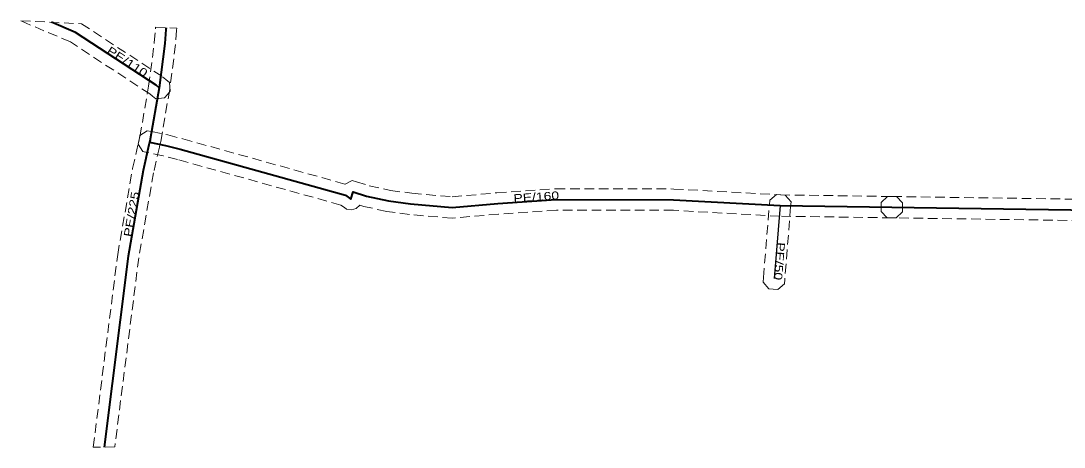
# Model space of a CAD drawing. Extents: x -701169 to -699809, y -1012430 to -1012137.
# Drawn here: x -700200.2 to -700102.4, y -1012429.8 to -1012389.8 of the extents above; entities that cross this region are included whole.
import ezdxf

# ---------------------------------------------------------------- set-up
doc = ezdxf.new("R2010")
doc.units = 0
doc.header["$LTSCALE"] = 0.3
doc.linetypes.add('MEDIUM_DASHED', pattern=[4.5, 3, -1.5])
doc.layers.add('1', color=7, linetype='MEDIUM_DASHED', lineweight=13)
doc.layers.add('24', color=7, linetype='Continuous', lineweight=40)
doc.layers.add('30', color=7, linetype='Continuous')

msp = doc.modelspace()

# ---------------------------------------------------------------- linework, layer by layer
at = {"layer": '1'}
for points in [[(-700200.203, -1012389.825), (-700194.524, -1012390.095), (-700186.926, -1012395.063), (-700186.604, -1012395.33), (-700186.284, -1012395.593), (-700186.205, -1012396.418), (-700186.469, -1012396.737), (-700186.732, -1012397.057), (-700187.557, -1012397.136), (-700187.876, -1012396.872), (-700188.114, -1012396.677), (-700195.564, -1012391.805)], [(-700191.401, -1012429.776), (-700193.419, -1012429.793), (-700191.129, -1012411.742), (-700189.731, -1012403.674), (-700189.179, -1012401.245), (-700189.123, -1012400.954), (-700189.045, -1012400.69), (-700189.044, -1012400.687), (-700188.229, -1012395.952), (-700187.695, -1012391.847), (-700187.597, -1012390.56), (-700187.587, -1012390.426), (-700185.589, -1012390.521), (-700185.603, -1012390.712), (-700185.705, -1012392.053), (-700186.251, -1012396.25), (-700187.095, -1012401.151), (-700187.129, -1012401.262), (-700187.177, -1012401.426), (-700187.221, -1012401.655), (-700187.769, -1012404.066), (-700189.151, -1012412.038)], [(-700185.01, -1012400.894), (-700169.822, -1012405.127), (-700169.136, -1012404.786), (-700168.752, -1012404.905), (-700167.542, -1012405.283), (-700165.566, -1012405.724), (-700163.56, -1012405.986), (-700159.781, -1012406.326), (-700155.589, -1012405.943), (-700150.073, -1012405.57), (-700138.992, -1012405.59), (-700129.015, -1012406.14), (-700118.547, -1012406.293), (-700118.133, -1012406.299), (-700117.556, -1012406.894), (-700117.562, -1012407.308), (-700117.568, -1012407.722), (-700118.163, -1012408.299), (-700118.577, -1012408.293), (-700129.085, -1012408.14), (-700139.048, -1012407.59), (-700150.007, -1012407.57), (-700155.431, -1012407.937), (-700159.779, -1012408.334), (-700163.78, -1012407.974), (-700165.914, -1012407.696), (-700168.058, -1012407.217), (-700168.437, -1012407.099), (-700168.77, -1012407.417), (-700168.996, -1012407.486), (-700169.222, -1012407.555), (-700169.688, -1012407.477), (-700169.879, -1012407.338), (-700170.213, -1012407.095), (-700185.53, -1012402.826), (-700186.878, -1012402.474), (-700188.352, -1012402.169), (-700188.758, -1012402.085), (-700189.213, -1012401.394), (-700189.129, -1012400.988), (-700189.045, -1012400.582), (-700188.354, -1012400.127), (-700187.948, -1012400.211), (-700186.422, -1012400.526)], [(-700128.02, -1012406.807), (-700128.053, -1012407.22), (-700128.603, -1012414.06), (-700128.636, -1012414.473), (-700129.267, -1012415.01), (-700129.68, -1012414.977), (-700130.093, -1012414.944), (-700130.63, -1012414.313), (-700130.597, -1012413.9), (-700130.047, -1012407.06), (-700130.014, -1012406.647), (-700129.383, -1012406.11), (-700128.97, -1012406.143), (-700128.557, -1012406.176)]]:
    msp.add_lwpolyline(points, close=True, dxfattribs=at)
msp.add_lwpolyline([(-700002.913, -1012408.1), (-700032.013, -1012408.18), (-700040.555, -1012408.28), (-700045.578, -1012408.37), (-700047.721, -1012408.47), (-700077.188, -1012408.81), (-700091.342, -1012408.69), (-700118.577, -1012408.293), (-700118.991, -1012408.287), (-700119.568, -1012407.692), (-700119.562, -1012407.278), (-700119.556, -1012406.864), (-700118.961, -1012406.287), (-700118.547, -1012406.293), (-700091.318, -1012406.69), (-700077.192, -1012406.81), (-700047.779, -1012406.47), (-700045.642, -1012406.37), (-700040.585, -1012406.28), (-700032.027, -1012406.18), (-700002.887, -1012406.1)], dxfattribs=at)
at = {"layer": '24', "lineweight": 25}
msp.add_line((-700129.05, -1012407.14), (-700129.6, -1012413.98), dxfattribs=at)
at = {"layer": '24'}
for points in [[(-700187.24, -1012396.101), (-700187.52, -1012395.87), (-700195.09, -1012390.92), (-700197.336, -1012389.962)], [(-700186.588, -1012390.473), (-700186.6, -1012390.636), (-700186.7, -1012391.95), (-700187.24, -1012396.101), (-700188.07, -1012400.92), (-700188.087, -1012400.976), (-700188.15, -1012401.19), (-700188.2, -1012401.45), (-700188.75, -1012403.87), (-700190.14, -1012411.89), (-700192.41, -1012429.785)], [(-700118.562, -1012407.293), (-700091.33, -1012407.69), (-700077.19, -1012407.81), (-700047.75, -1012407.47), (-700045.61, -1012407.37), (-700040.57, -1012407.28), (-700032.02, -1012407.18), (-700002.9, -1012407.1), (-699984.94, -1012407.63), (-699970.64, -1012408.03), (-699952.89, -1012407.83), (-699944.26, -1012407.4), (-699939.86, -1012407.09), (-699903.84, -1012405.22), (-699856.61, -1012400.09), (-699836.62, -1012397.69), (-699817.82, -1012395.72), (-699809.132, -1012395.385)], [(-700188.15, -1012401.19), (-700186.65, -1012401.5), (-700185.27, -1012401.86), (-700169.77, -1012406.18), (-700169.29, -1012406.53), (-700169.05, -1012405.86), (-700167.8, -1012406.25), (-700165.74, -1012406.71), (-700163.67, -1012406.98), (-700159.78, -1012407.33), (-700155.51, -1012406.94), (-700150.04, -1012406.57), (-700139.02, -1012406.59), (-700129.05, -1012407.14), (-700118.562, -1012407.293)]]:
    msp.add_lwpolyline(points, dxfattribs=at)

# ---------------------------------------------------------------- texts
at = {"layer": '30', "width": 1.3}
for s, rotation, p in [('PE/110', 326.819, (-700192.217, -1012392.799)), ('PE/225', 80.167, (-700189.834, -1012410.123)), ('PE/160', 3.87, (-700154.003, -1012406.838)), ('PE/50', 265.403, (-700129.325, -1012410.56))]:
    msp.add_text(s, height=0.75, rotation=rotation, dxfattribs=at).set_placement(p)

doc.saveas('drawing.dxf')
